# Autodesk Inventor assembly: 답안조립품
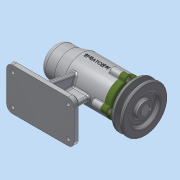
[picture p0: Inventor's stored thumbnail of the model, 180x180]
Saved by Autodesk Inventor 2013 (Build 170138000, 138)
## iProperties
Created: 2019-07
Part Number: 답안조립품
Document SubType Name: Assembly
Designer: Administrator
Author: Administrator
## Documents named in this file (12)
- D:\490704V1013\답안조립품.iam
- D:\490704V1013\본체.ipt
- D:\490704V1013\V벨트풀리.ipt
- D:\490704V1013\멈춤나사 M3.ipt
- D:\490704V1013\베어링 6004.ipt
- D:\490704V1013\베어링 51202.ipt
- D:\490704V1013\볼트 M4.ipt
- D:\490704V1013\어댑터슬리브.ipt
- D:\490704V1013\오일 실.ipt
- D:\490704V1013\축.ipt
- D:\490704V1013\커버.ipt
- D:\490704V1013\키 5 x 5 x 16.ipt
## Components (1 placed, 1 different names)
1. V벨트풀리:1
